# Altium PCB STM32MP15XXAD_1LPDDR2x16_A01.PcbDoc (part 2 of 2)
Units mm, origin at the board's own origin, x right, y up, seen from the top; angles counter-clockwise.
Board outline 86 x 120 mm, 4 copper layers (Top Layer, Signal Layer 1, Signal Layer 2, Bottom Layer), stack 1.571 mm thick; 88 components, 79 nets, 759 pads, 355 vias.
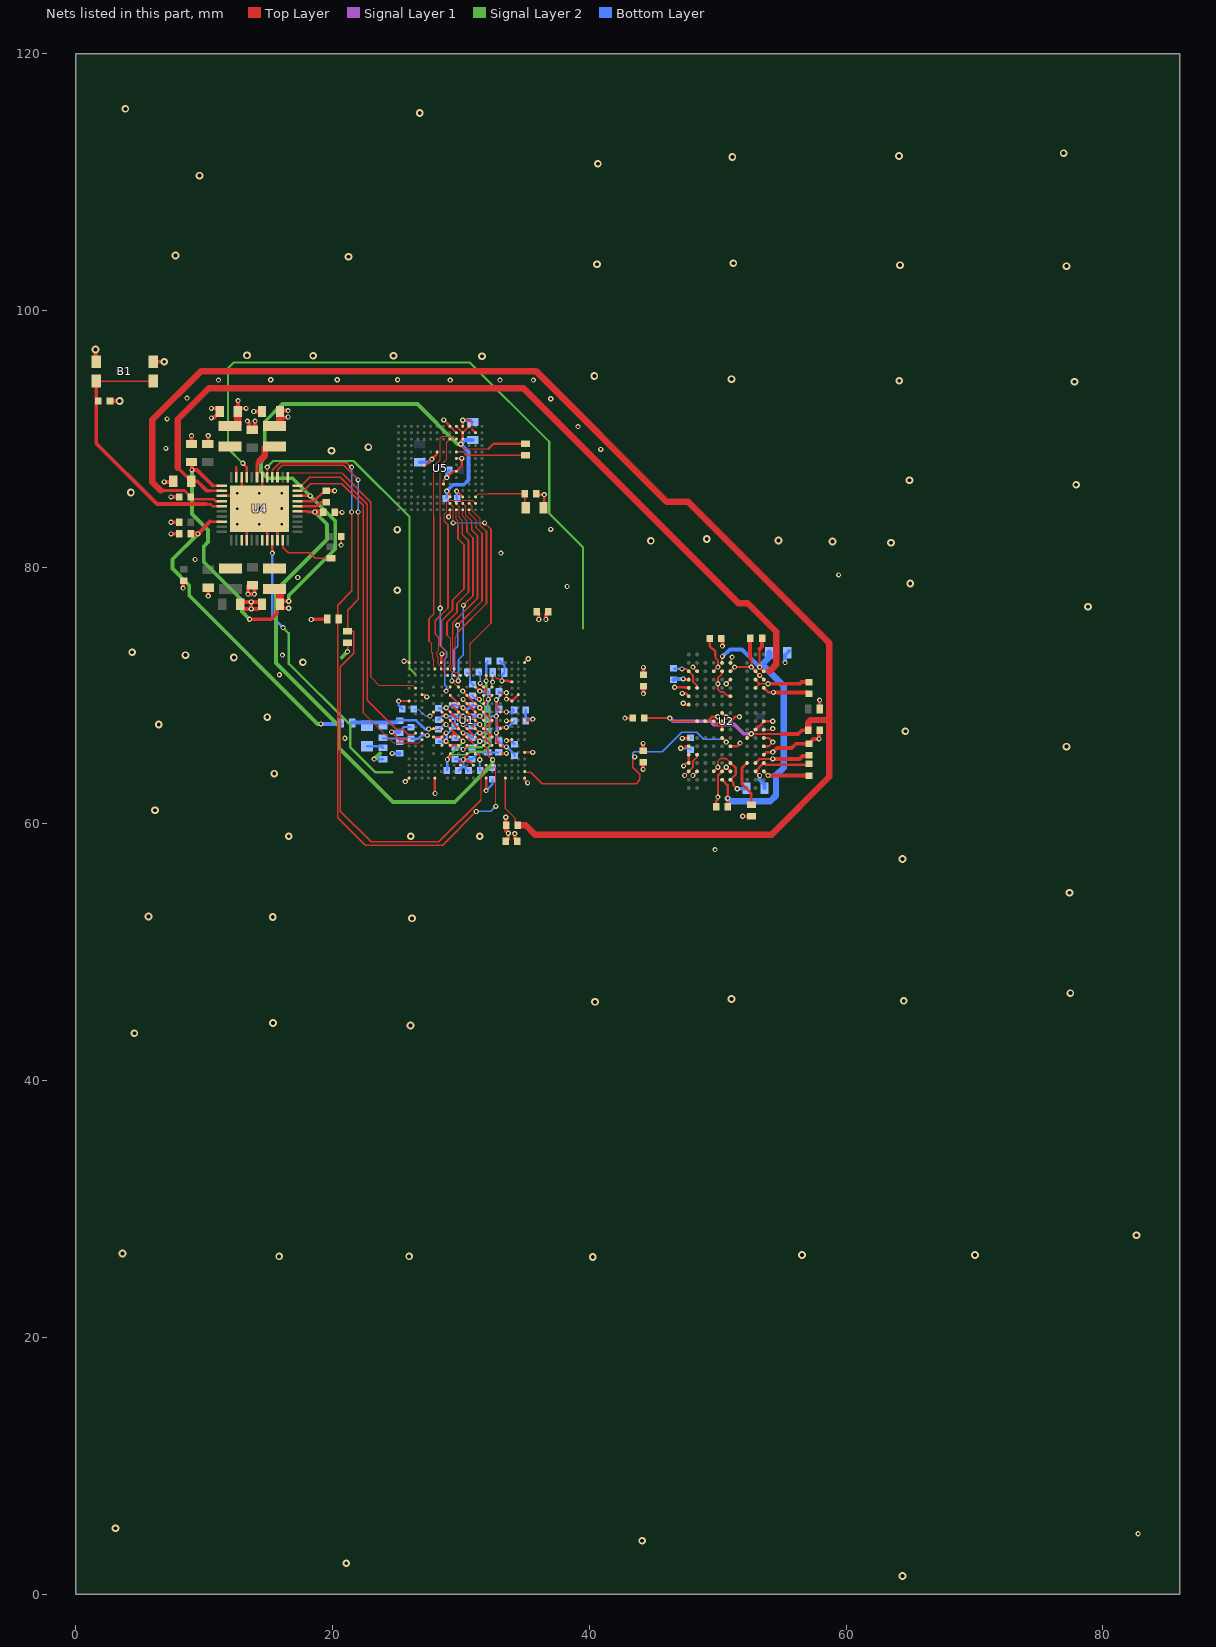
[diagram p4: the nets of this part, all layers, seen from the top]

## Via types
v1: diameter 0.4, hole 0.2, Top Layer to Bottom Layer, tented both sides, 276 vias
v2: diameter 0.6, hole 0.3, Top Layer to Bottom Layer, tented both sides, 74 vias
v3: diameter 0.4, hole 0.2, Top Layer to Bottom Layer, 3 vias
v4: diameter 0.4, hole 0.2, Top Layer to Signal Layer 1, tented top, 2 vias

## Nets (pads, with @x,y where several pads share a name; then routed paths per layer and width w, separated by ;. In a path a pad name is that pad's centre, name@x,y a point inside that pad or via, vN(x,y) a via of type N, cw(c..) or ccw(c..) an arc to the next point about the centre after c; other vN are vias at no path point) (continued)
DDR_DQS1_P: U1.V19 U2.G6 | length 20.7
  Top Layer w0.1: U1.V19@34.97,64.08 U1.V19@34.975,64.075 35,64.05 35.45,64.05 36.355,63.145 39.97,63.145 43.645,63.145 43.955,63.455 43.955,63.87 43.396,64.429 43.396,65.071 v1(43.55,65.225) ; U2.G6@50.35,66.7 v1(50.675,66.375)
  Bottom Layer w0.1: v1(43.55,65.225) 43.396,65.379 43.396,65.521 43.504,65.629 45.704,65.629 47.215,67.14 48.385,67.14 48.94,66.585 50.465,66.585 v1(50.675,66.375)
eMMC_SDIO2_D0: U1.1A4 U5.A3 | length 15.5
  Top Layer w0.09: v1(29.3,71.15) 29.8,70.65 29.825,70.625 29.875,70.625 U1.1A4@29.875,70.645 ; U5.A3@30.65,84.475 30.65,84.2 31.188,83.662 31.188,83.087
  Top Layer w0.13: v1(29.75,75.475) 31.65,77.375 31.65,82.625 31.188,83.087
  Bottom Layer w0.13: v1(29.3,71.15) 29.3,71.725 29.475,71.9 29.475,73.575 29.75,73.85 v1(29.75,75.475)
eMMC_SDIO2_D1: U1.C8 U5.A4 | length 14.7
  Top Layer w0.09: U1.C8@29.475,71.575 29.8,71.25 v1(29.8,71.15) ; U5.A4@30.15,84.475 30.15,83.95 30.475,83.625 30.475,83.25
  Top Layer w0.13: v1(30.2,77.025) 30.95,77.775 30.95,82.275 30.475,82.75 30.475,83.25
  Bottom Layer w0.09: 30.175,73.15 30.2,73.175
  Bottom Layer w0.13: v1@29.825,71.15 29.825,72.8 30.175,73.15 ; 30.2,73.175 v1(30.2,77.025)
eMMC_SDIO2_D2: U1.C7 U5.A5 | length 14.2
  Top Layer w0.09: 28.525,74.4 28.525,73.775 28.875,73.425 28.875,72.975 28.725,72.825 28.725,71.815 28.965,71.575 U1.C7@28.975,71.575 ; U5.A5@29.65,84.475 29.65,83.725 29.775,83.6 29.775,83.25
  Top Layer w0.13: 28.525,74.4 28.525,75.85 29.35,76.675 29.35,77.425 30.25,78.325 30.25,81.75 29.775,82.225 29.775,83.25
eMMC_SDIO2_D3: U1.B6 U5.B2 | length 16.3
  Top Layer w0.09: 28.275,73.85 28.275,73.55 28.17,73.445 28.17,73.059 28.23,72.999 28.23,72.474 28.374,72.33 28.425,72.33 28.475,72.28 U1.B6@28.475,72.075 ; 28.7,83.6 28.7,84.125 28.9,84.325 28.9,85.064 29.061,85.225 30.9,85.225 U5.B2@31.15,84.975
  Top Layer w0.13: 28.275,73.85 28.275,74.525 28,74.8 28,75.825 29,76.825 29,83.3 28.7,83.6
eMMC_SDIO2_D4: U1.B8 U5.B3 | length 14.5
  Top Layer w0.09: U1.B8@29.475,72.075 29.56,72.16 29.56,74.535 29.725,74.7 29.725,74.9 ; U5.B3@30.65,84.975 30.65,84.965 30.9,84.715 30.9,84.386 31.5,83.786 31.5,83.275
  Top Layer w0.13: 29.725,74.9 32,77.175 32,82.775 31.5,83.275
eMMC_SDIO2_D5: U1.C9 U5.B4 | length 15.3
  Top Layer w0.09: 29.39,74.71 29.39,72.336 29.23,72.176 29.23,71.95 29.355,71.825 29.725,71.825 U1.C9@29.975,71.575 ; U5.B4@30.15,84.975 30.4,84.725 30.4,84.05 30.85,83.6 30.85,83.25
  Top Layer w0.1: 29.39,74.71 29.39,75.665
  Top Layer w0.13: 29.39,75.665 31.3,77.575 31.3,82.45 30.85,82.9 30.85,83.25
eMMC_SDIO2_D6: U1.B7 U5.B5 | length 14.2
  Top Layer w0.09: 28.925,74.715 29.22,74.42 29.22,72.445 28.975,72.2 U1.B7@28.975,72.075 ; U5.B5@29.65,84.975 29.65,84.965 29.89,84.725 29.89,83.86 30.1,83.65 30.1,83.25
  Top Layer w0.13: 28.925,74.715 28.925,75.725 29.7,76.5 29.7,77.166 30.6,78.066 30.6,82.05 30.1,82.55 30.1,83.25
eMMC_SDIO2_D7: U1.C10 U5.B6 | length 16.9
  Top Layer w0.09: U5.B6@29.15,84.975 29.4,84.725 v1(29.4,83.45) ; U1.C10@30.475,71.575 30.72,71.82 30.72,74.02
  Top Layer w0.13: 30.72,74.02 32.35,75.65 32.35,82.95 v1(31.85,83.45)
  Bottom Layer w0.09: v1(29.4,83.45) v1(31.85,83.45)
GND: B1.1 B1.2 C1.1 C2.1 C3.1 C4.1 C5.1 C6.1 C7.1 C8.1 C9.1 C10.2 C11.2 C12.2 C13.1 C14.1 C15.2 C16.2 C17.2 C18.1 C19.2 C20.2 C21.2 C22.2 C23.2 C24.2 C25.1 C26.2 C27.1 C28.2 C29.1 C30.1 C31.1 C32.1 C33.1 C34.1 C35.1 C36.1 C37.1 C38.1 C39.1 C40.1 C41.1 C42.1 C43.1 C44.1 C45.1 C46.1 C47.1 C48.1 C49.1 C50.1 C51.2 C52.1 C53.1 C54.1 C55.1 C56.1 C57.1 C58.1 C59.1 C60.1 C61.1 C78.1 C79.1 C80.1 C81.1 C82.1 C83.1 R1.2 R14.1 R31.2 U1.1A6 U1.1B8 U1.1C3 U1.1C5 U1.1C7 U1.1D2 U1.1D4 U1.1D6 U1.1E3 U1.1E5 U1.1E7 U1.1F4 U1.1F6 U1.1G1 U1.1G2 U1.1G5 U1.1G7 U1.1H2 U1.1H3 U1.1H4 U1.1H6 U1.1H8 U1.1J5 U1.1J9 U1.A1 U1.A6 U1.A19 U1.C14 U1.D17 U1.F3 U1.F18 U1.G1 U1.G17 U1.K17 U1.K19 U1.N1 U1.N17 U1.R19 U1.U9 U1.U11 U1.W1 U1.W5 U1.W13 U1.W19 U2.C2 U2.C5 U2.C6 U2.C9 U2.D1 U2.D10 U2.E1 U2.E10 U2.F5 U2.G10 U2.H2 U2.J1 U2.J5 U2.J8 U2.L10 U2.M5 U2.N1 U2.N10 U2.P1 U2.P10 U2.R2 U2.R5 U2.R6 U2.R9 U4.6 U4.10 U4.15 U4.26 U4.30 U4.32 U4.41 U4.ep U5.A6 U5.C4 U5.E7 U5.G5 U5.H10 U5.J5 U5.K8 U5.N2 U5.N5 U5.P4 U5.P6 | length 156.4
  Top Layer w0.09: 30.675,91.45 30.9,91.225 30.9,90.725
  Top Layer w0.12: U1.1C5@30.51,69.34 U1.1C5@30.52,69.33 ; U1.C14@32.475,71.575 32.559,71.575 32.834,71.3 33.025,71.3 33.188,71.138 v1@33.25,71.075 ; U2.J8@49.05,67.965 U2.J8@49.165,67.965 ; U2.M5@50.96,69.95 U2.M5@51,69.95 U2.M5@51,69.985 ; C11.2@52.525,74.435 C11.2@52.56,74.47
  Top Layer w0.15: U1.A19@34.97,72.58 v1@35.258,72.867 ; v1(48.075,72.225) U2.R9@48.4,71.9 ; v1(50.025,62.1) 50.025,63.775 ; U2.R6@50.35,71.9 50.35,71.7 50.025,71.375 v1(50.025,70.925) 50.025,70.479 50.229,70.275 50.475,70.275 50.75,70 50.95,70 U2.M5@51,69.95 ; v1(51.325,72.225) v1(52.625,72.225) 52.625,72.875
  Top Layer w0.175: B1.1@1.55,96.05 B1.1@1.6,96 B1.1@1.6,96.25 ; C60.1@7.55,86.65 C60.1@7.6,86.7 ; C32.1@8.375,78.9 C32.1@8.425,78.95 ; C18.1@10.3,89.6 C18.1@10.325,89.625 ; C29.1@10.975,92.375 C29.1@11.225,92.125 ; C40.1@13.025,77.3 C40.1@12.825,77.1 13.175,76.75 ; C33.1@13.75,90.7 C33.1@13.975,90.925 ; C31.1@13.775,78.6 C31.1@13.925,78.45 ; 14.175,76.75 C38.1@14.525,77.1 C38.1@14.325,77.3 ; C52.1@20.175,84.275 v1(20.75,84.275) ; v1(20.675,81.725) C51.2@20.675,82.4 ; v1(24.6,67.175) 25.2,66.575 U1.N1@25.975,66.575 ; v1(25.15,69.575) U1.G1@25.975,69.575 ; v1(25.575,72.675) 25.875,72.675 U1.A1@25.975,72.575 ; v1(25.675,63.3) 25.7,63.3 U1.W1@25.975,63.575 ; U1.F3@26.975,70.075 27.175,70.075 v1(27.35,69.9) v1@27.4,69.9 ; U5.H10@27.15,87.975 27.3,87.975 v1(27.75,88.425) 28.15,88.825 U5.K8@28.15,88.975 ; U1.1G1@27.875,66.775 U1.1G2@28.525,66.775 ; v1@27.975,62.425 U1.W5@27.975,63.575 ; U1.A6@28.475,72.575 28.475,73.2 v1(28.525,73.25) ; U1.1H2@28.525,66.125 v1(28.85,66.45) ; U1.1D2@28.575,68.675 v1(28.85,68.4) U1.1E3@29.175,68.075 U1.1F4@29.825,67.425 30.162,67.088 U1.1G5@30.475,66.775 U1.1H6@31.125,66.125 ; U5.E7@28.65,86.475 28.65,86.725 v1(28.9,86.975) 29.4,87.475 U5.G5@29.65,87.475 30.075,87.9 v1(30.075,88.475) U5.J5@29.65,88.475 ; v1(28.675,91.475) 29.15,91 U5.P6@29.15,90.975 U5.N5@29.65,90.475 ; v1(28.85,67.1) U1.1G2@28.525,66.775 ; v1@28.9,66.425 v1@28.9,66.4 ; v1(29.05,83.925) 29.15,84.025 U5.A6@29.15,84.475 ; U1.1C3@29.225,69.325 U1.1D4@29.825,68.725 30.162,68.388 U1.1E5@30.475,68.075 U1.1F6@31.125,67.425 31.462,67.088 U1.1G7@31.775,66.775 U1.1H8@32.425,66.125 ; v1(29.675,85.925) 29.7,85.925 U5.C4@30.15,85.475 ; U1.1H4@29.825,66.125 U1.1H3@29.175,66.125 v1@28.9,66.4 ; U1.U9@29.975,64.575 29.975,64.825 30.188,65.038 30.2,65.05 30.212,65.038 30.367,64.883 30.668,64.883 U1.U11@30.975,64.575 ; U5.P4@30.15,90.948 U5.P4@30.15,90.975 v1(30.15,91.45) 30.675,91.45 ; v1@30.175,65.075 U1.1J5@30.525,65.425 ; v1@30.2,69.625 30.225,69.625 U1.1C5@30.475,69.375 U1.1C5@30.51,69.34 ; U1.1C5@30.52,69.33 30.825,69.025 ; 30.83,69.02 U1.1D6@31.125,68.725 31.462,68.388 U1.1E7@31.775,68.075 ; 30.9,90.725 U5.N2@31.15,90.475 ; U1.1A6@31.15,70.675 v1(31.475,70.35) ; U1.1C7@31.775,69.375 32.125,69.725 v1@32.15,69.75 ; v1(31.975,62.6) U1.W13@31.975,63.575 ; v1(32.15,69.7) v1@32.15,69.75 ; U1.1B8@32.425,70.025 v1@32.15,69.75 ; U1.1J9@33.075,65.475 33.525,65.475 v1(33.55,65.5) ; v1@33.125,81 v1(33.125,81.1) ; v1(33.2,71.15) 33.673,71.15 33.748,71.075 U1.D17@33.975,71.075 ; C8.1@33.5,59.925 C8.1@33.525,59.9 ; v1(33.55,68.025) 33.925,68.025 U1.K17@33.975,68.075 ; v1(33.55,69.725) 33.825,69.725 U1.G17@33.975,69.575 ; v1@33.575,66.575 33.55,66.55 33.575,66.525 33.6,66.5 33.9,66.5 U1.N17@33.975,66.575 ; U1.W19@34.975,63.575 34.975,63.425 v1(35.2,63.2) ; U1.K19@34.975,68.075 35.5,68.075 v1(35.6,68.175) ; C82.1@35.875,85.725 35.95,85.65 v1(36.5,85.65) 36.5,84.675 C83.1@36.45,84.625 ; C23.2@44.2,64.796 C23.2@44.215,64.81 ; v1(47.35,64.525) 47.575,64.75 U2.D10@47.75,64.75 U2.D10@47.725,64.725 ; 50.025,63.775 U2.C6@50.35,64.1 v1(50.675,64.425) ; C20.2@50.275,74.45 50.275,74.425 C20.2@50.375,74.325 ; v1(50.675,64.425) U2.C5@51,64.1 ; U2.J1@53.6,68 v1(54.3,68) ; U1.1G2@28.525,66.775 v1(28.85,66.45) ; v1(28.85,66.45) v1@28.9,66.4 ; v1(28.85,66.45) 28.875,66.425 v1@28.9,66.4
  Top Layer w0.2: U4.15@11.375,85.55 12.6,85.55 U4.ep@13.325,85.55 ; U4.10@12.925,87 12.925,85.95 U4.ep@13.325,85.55 ; U4.26@13.325,82.1 13.325,83.55 U4.ep@14.325,84.55 ; U4.6@14.525,87 14.525,85.75 14.525,84.75 U4.ep@14.325,84.55 ; U4.30@14.925,82.1 U4.ep@14.925,83.95 ; U4.32@15.725,82.1 15.725,83.15 U4.ep@14.925,83.95 ; U4.41@17.275,85.15 18.575,85.15 19.375,85.95 C43.1@19.525,85.95 ; U1.1D2@28.57,68.68 U1.1D2@28.575,68.675 ; U1.G17@33.975,69.575 34.46,70.06 34.46,70.075 U1.F18@34.46,70.08 ; U1.R19@34.97,65.58 34.975,65.58 v1@35.6,65.58 ; v1(42.775,68.25) C26.2@43.375,68.25 ; v1(46.65,70.65) 47.5,70.65 47.55,70.6 U2.N10@47.75,70.6 ; v1@47.25,66.7 U2.G10@47.75,66.7 ; v1(47.325,69.4) 47.425,69.3 U2.L10@47.75,69.3 ; v1(47.325,71.3) 47.375,71.3 47.425,71.25 U2.P10@47.75,71.25 ; U2.D10@47.75,64.75 U2.E10@47.75,65.4 ; v1(48.075,63.775) U2.C9@48.4,64.1 ; U2.J8@49.165,67.965 49.55,68.35 v1(50,68.35) ; C10.2@49.88,61.35 49.88,61.78 50.025,61.925 v1(50.025,62.1) ; U2.F5@51,66.05 51.5,66.05 v1(51.75,66.3) ; U2.J5@51,68 51.35,68.35 v1(51.7,68.35) ; U2.R5@51,71.9 v1(51.325,72.225) ; v1(52.625,72.225) U2.R2@52.95,71.9 v1(53.275,71.575) U2.P1@53.6,71.25 ; U2.H2@52.95,67.35 U2.J1@53.6,68 ; v1(53.275,63.775) U2.C2@52.95,64.1 53.55,64.7 53.6,64.7 53.675,64.7 53.75,64.625 57.1,64.625 C12.2@57.125,64.6 ; U2.E1@53.6,65.4 53.8,65.6 v1(54.3,65.6) ; U2.N1@53.6,70.6 53.95,70.25 v1@54.345,70.25 ; U4.ep@13.325,85.55 v1(14.3,84.575) U4.ep@14.325,84.55 ; U4.ep@14.325,84.55 U4.ep@14.925,83.95
  Top Layer w0.25: v4(7.425,82.6) C49.1@8.075,82.6 ; v4(7.425,83.5) C41.1@8.075,83.5 ; v1(10.325,77.75) C39.1@10.325,78.4 ; C43.1@19.525,85.95 v1(20.175,85.95)
  Top Layer w0.3: B1.1@1.55,96.05 v2(1.55,96.95) ; C44.1@2.675,92.95 v2(3.425,92.95) ; B1.2@6.05,96 v2(6.9,96) ; v1(6.9,86.65) C60.1@7.55,86.65 ; v1(7.425,85.475) C27.1@8.075,85.475 ; v1(8.375,78.375) C32.1@8.375,78.9 ; C42.1@9.025,89.6 v1(9.025,90.25) ; C18.1@10.325,89.625 v1(10.325,90.25) ; v1(10.575,91.625) 10.725,91.625 C29.1@11.225,92.125 ; v1(10.575,92.375) C29.1@10.975,92.375 ; C40.1@13.025,77.3 v1(13.675,77.3) ; 13.175,76.75 v1(13.675,76.75) ; v1(13.375,91.375) 13.55,91.2 C33.1@13.55,90.925 ; v1(13.425,77.9) C31.1@13.425,78.55 ; v1(13.875,92.125) C34.1@14.525,92.125 ; v1(13.925,77.9) C31.1@13.925,78.45 ; C33.1@13.975,90.925 v1(13.975,91.375) ; 14.175,76.75 v1(13.675,76.75) ; C38.1@14.325,77.3 v1(13.675,77.3) ; C24.2@33.5,58.65 33.7,58.85 v1(33.7,59.275) 33.525,59.45 C8.1@33.525,59.9 ; C8.1@33.5,59.925 v1(33.5,60.525) ; v1(36.625,75.925) 36.625,76.35 C21.2@36.8,76.525 ; v1(44.2,64.25) C23.2@44.2,64.796 ; C22.2@44.225,71.625 v1(44.225,72.2) ; v3(50.375,73.85) C20.2@50.375,74.325 ; v1(51.95,60.6) R31.2@52.625,60.6 ; C11.2@52.525,74.435 52.525,72.975 52.625,72.875 ; v1(54.3,65.6) 54.625,65.925 55.765,65.925 56.09,66.25 57.1,66.25 57.113,66.263 57.475,66.625 v1(57.9,66.625) 57.9,67.225 57.963,67.288 C28.2@57.975,67.3 ; v1@54.345,70.25 v1(54.35,70.25) 57.025,70.25 C19.2@57.125,70.15 ; R14.1@57.95,68.975 v1(57.95,69.65) ; v1(13.675,76.75) v1(13.675,77.3)
  Top Layer w0.33: v1(13.425,77.9) v1(13.925,77.9)
  Bottom Layer w0.175: C2.1@25.075,67.175 C2.1@25.2,67.175 ; v1(25.15,69.575) 25.15,69.25 C1.1@25.45,68.95 ; C2.1@25.175,67.075 25.191,67.14 C2.1@25.2,67.175 ; C50.1@25.225,65.5 C50.1@25.25,65.525 ; C2.1@25.25,67.125 C2.1@25.2,67.175 ; C61.1@26.125,67.55 25.575,67.55 C2.1@25.2,67.175 ; C36.1@28.25,68.125 28.525,68.4 v1(28.85,68.4) C35.1@29.55,68.4 ; C47.1@28.275,66.425 28.3,66.4 28.85,66.4 v1@28.925,66.4 ; v1@28.825,66.975 v1@28.9,67.05 ; v1@28.9,66.45 v1@28.9,67.05 ; v1@28.925,67.075 v1@28.9,67.05 ; C46.1@29.525,67.625 29.55,67.65 C35.1@29.55,68.35 C35.1@29.55,68.4 ; C4.1@29.55,65.025 29.562,65.037 29.575,65.05 v1@30.2,65.05 ; C46.1@29.55,67.6 29.625,67.6 30.15,67.075 v1@30.175,67.05 ; C46.1@29.55,67.625 29.537,67.612 28.975,67.05 v1@28.9,67.05 ; v1(29.675,85.925) 29.675,85.4 C80.1@29.725,85.35 ; C48.1@29.825,64.15 30.2,64.525 ; v1@30.2,67.05 30.525,67.05 C13.1@30.8,66.775 ; C6.1@30.475,71.75 30.725,71.5 30.725,71.075 C5.1@30.9,70.9 31.45,70.35 v1(31.475,70.35) ; C3.1@30.575,64.15 30.2,64.525 ; C81.1@30.775,91.45 C81.1@30.925,91.3 ; C13.1@30.85,66.675 C13.1@30.875,66.7 31.275,67.1 v1(31.475,67.1) 32,67.1 C58.1@32.125,67.225 ; v1(31.475,68.4) 30.925,68.4 C14.1@30.875,68.35 30.825,68.4 v1(30.175,68.4) 29.552,68.4 C35.1@29.55,68.4 ; v1@31.5,68.35 31.512,68.362 C57.1@32.075,68.925 ; v1@31.5,70.3 32.05,70.3 C53.1@32.075,70.325 C53.1@32.125,70.275 ; v1(31.975,62.6) 32.475,63.1 C7.1@32.475,63.475 ; C57.1@32.075,68.95 C57.1@32.075,68.925 ; C30.1@32.1,65.625 C30.1@32.1,65.575 ; C57.1@32.15,69 C57.1@32.125,68.975 ; C53.1@32.15,70.25 C53.1@32.125,70.275 ; C45.1@33.05,72.7 33.4,72.35 R1.2@33.4,71.8 33.2,71.6 v1(33.2,71.15) ; v1(33.55,65.5) 33.025,65.5 C59.1@32.95,65.575 C30.1@32.1,65.575 ; v1(33.55,66.5) 33.9,66.5 C55.1@34.175,66.225 ; C56.1@35.05,68.875 C54.1@35.05,68.025 35.2,68.175 v1(35.6,68.175) ; v1(47.25,66.67) 47.87,66.67 C15.2@47.9,66.7 ; 30.2,64.525 v1(30.2,65.025) v1@30.2,65.05 ; v1@30.2,65.05 C37.1@30.875,65.05 31.4,65.575 C30.1@32.1,65.575 ; C57.1@32.075,68.925 32.087,68.937 C57.1@32.125,68.975 ; C57.1@32.125,68.975 32.125,69.7 C53.1@32.125,70.275
  Bottom Layer w0.3: v1(24.6,67.175) C2.1@25.2,67.175 ; v1(24.65,65.5) C50.1@25.225,65.5 ; C79.1@26.8,88.175 27.5,88.175 v1(27.75,88.425) ; v1(28.9,86.975) 28.9,87.35 C78.1@29.1,87.55 ; v1(30.15,91.45) C81.1@30.775,91.45 ; C16.2@46.575,71.225 46.65,71.3 v1(47.325,71.3) ; v1(53.275,63.775) 53.275,63.45 53.65,63.075 C25.1@53.65,62.8 ; v1(55.25,72.575) 55.25,73.155 C9.1@55.43,73.335 C9.1@55.573,73.479
  other v1: 82.75,4.725 49.8,58 28,62.375 35.6,65.575 20.975,66.675 30.175,67.1 30.175,69.7 15.875,71.625 35.25,72.875 16.1,73.15 17.3,79.2 59.425,79.4 9.3,80.6 37,82.95 12.6,83.35 14.3,83.35 16.05,83.35 12.575,84.55 16.05,84.575 12.6,85.75 14.3,85.75 16.05,85.75 40.9,89.175 7.025,89.25 39.125,90.95 7.125,91.55 37,93.125 8.675,93.175 11.125,94.575 29.175,94.575 33.05,94.575 35.65,94.575 15.2,94.6 20.375,94.6 25.075,94.6
  other v2: 64.4,1.425 21.075,2.425 44.125,4.175 3.1,5.15 40.275,26.275 15.85,26.325 25.975,26.325 56.575,26.425 70.05,26.425 3.65,26.55 82.625,27.975 4.575,43.7 26.075,44.3 15.375,44.5 40.45,46.15 64.5,46.225 51.075,46.375 77.475,46.825 26.2,52.65 15.35,52.75 5.675,52.8 77.4,54.65 64.4,57.275 16.6,59.05 26.1,59.05 31.475,59.05 6.175,61.075 15.475,63.925 77.175,66.025 64.625,67.225 6.475,67.75 14.925,68.325 17.7,72.6 12.325,72.975 8.55,73.15 4.4,73.375 78.85,76.925 25.05,78.2 65,78.725 63.5,81.9 58.95,82 44.8,82.05 54.75,82.075 49.15,82.2 25.05,82.925 4.3,85.825 77.925,86.425 64.95,86.775 19.925,89.075 22.8,89.35 77.8,94.45 64.15,94.525 51.075,94.65 40.4,94.9 31.65,96.425 18.5,96.475 24.75,96.475 13.35,96.5 77.175,103.45 64.2,103.525 40.6,103.6 51.225,103.675 21.25,104.175 7.775,104.275 9.65,110.5 40.675,111.425 51.15,111.95 64.125,112.025 76.95,112.25 26.8,115.375 3.875,115.7
  other v3: 38.275,78.5
I2C4_SCL: R37.2 U1.U14 U4.4 | length 52.6
  Top Layer w0.09: 15.3,87.54 15.3,87.025 U4.4@15.325,87 ; U1.U14@32.475,64.575 32.72,64.33 v1@32.72,61.425
  Top Layer w0.1: 15.3,87.54 15.885,88.125 21.1,88.125 21.425,87.8 v1(21.5,87.8) ; v1(21.5,84.3) 21.5,78.15 20.4,77.05 20.4,75.95 20.4,60.5 22.55,58.35 28.575,58.35 v1(31.2,60.975)
  Bottom Layer w0.1: v1(21.5,84.3) v1(21.5,87.8) ; v1(31.2,60.975) 32.325,60.975 v1(32.725,61.375)
I2C4_SDA: R38.2 U1.U13 U4.3 | length 50.7
  Top Layer w0.09: U4.3@15.725,87 15.725,87.575 ; 31.575,61.9 31.575,63.762 31.72,63.907 31.72,64.166 31.975,64.421 U1.U13@31.975,64.575
  Top Layer w0.1: 15.725,87.575 16.075,87.925 20.875,87.925 v1(22,86.8) ; v1@22.025,84.275 22.025,77.5 21.175,76.65 R38.2@21.175,75 21.675,75 21.675,73.3 20.625,72.25 20.625,61 23.025,58.6 28.275,58.6 31.575,61.9
  Bottom Layer w0.1: v1(22,84.3) v1(22,86.8)
NetB1_3: B1.3 B1.4 C44.2 U4.17 | length 21.5
  Top Layer w0.1: B1.3@1.325,94.775 B1.3@1.6,94.5 B1.4@6.05,94.5
  Top Layer w0.2: 10.125,84.9 10.525,84.9 10.675,84.75 U4.17@11.375,84.75
  Top Layer w0.3: B1.3@1.6,94.45 1.6,92.95 1.6,89.65 6.325,84.925 10.15,84.925
NetC1_2: C1.2 U1.1D1 | length 1.9
  Top Layer w0.09: v1(27.6,68.4) 27.65,68.4 27.925,68.675 U1.1D1@27.925,68.65
  Bottom Layer w0.09: C1.2@26.375,68.95 26.7,68.95 27.225,68.425 27.55,68.425 27.587,68.388 v1@27.6,68.375
NetC2_2: C2.2 L5.2 R41.1 R42.2 U1.1F1 U1.1F2 | length 7.4
  Top Layer w0.09: v1@27.5,67.375 27.875,67.375 28.525,67.375 U1.1F2@28.575,67.375
  Bottom Layer w0.2: C2.2@25.075,68.075 25.25,68.075 26.525,68.075 27.2,67.4 v1(27.5,67.4)
  Bottom Layer w0.3: R42.2@21.55,67.9 22.7,67.9 23.925,67.9 24.9,67.9 C2.2@25.075,68.075
NetC3_2: C3.2 U1.1J6 | length 1.7
  Top Layer w0.09: v1@31.5,65 v1@31.5,65.1
  Top Layer w0.1: U1.1J6@31.175,65.425 31.4,65.425 31.475,65.35 v1(31.475,65) v1@31.5,65
  Bottom Layer w0.1: C3.2@31.475,64.175 v1(31.475,65)
  Bottom Layer w0.175: C3.2@31.5,64.2 31.512,64.188 C3.2@31.525,64.175
NetC6_2: C6.2 U1.1A7 U1.1B7 | length 2.1
  Top Layer w0.2: v1(31.5,70.95) U1.1A7@31.775,70.675 31.95,70.5 31.95,70.2 U1.1B7@31.775,70.025
  Bottom Layer w0.1: C6.2@31.4,71.85 31.5,71.75 v1(31.5,70.95)
NetC43_2: C43.2 U4.40 | length 2.4
  Top Layer w0.2: U4.40@17.275,84.75 18.775,84.75 19.075,85.05 C43.2@19.525,85.05
NetC82_2: C82.2 C83.2 U5.C2 | length 5.1
  Top Layer w0.09: U5.C2@31.15,85.475 31.4,85.725 32.15,85.725
  Top Layer w0.1: 32.15,85.725 C82.2@34.975,85.725 34.975,84.7 C83.2@35.05,84.625
NetL1_1: L1.1 U4.7 | length 3.2
  Top Layer w0.2: U4.7@14.125,87 14.125,88.1 14.325,88.3
  Top Layer w0.5: 14.325,88.3 14.725,88.7 14.725,89.3 14.825,89.4 L1.1@15.325,89.4
NetL2_1: L2.1 U4.11 | length 0.8
  Top Layer w0.2: U4.11@12.525,87 12.525,87.8
NetL3_1: L3.1 U4.29
NetL4_1: L4.1 U4.25
NetL5_1: L5.1 R39.2 | length 1.3
  Bottom Layer w0.2: L5.1@22.7,66.05 23.825,66.05 R39.2@23.925,65.95
NetR1_1: R1.1 U1.1A8 | length 1.1
  Top Layer w0.09: U1.1A8@32.425,70.675 32.425,71 v1(32.475,71.05)
  Bottom Layer w0.175: v1(32.475,71.05) R1.1@32.475,71.8
NetR31_1: R31.1 U2.D3 | length 3.7
  Top Layer w0.2: U2.D3@52.3,64.75 51.9,64.35 51.9,63.1 52.625,62.375 R31.1@52.625,61.5
NetR40_1: R40.1 U5.K5 | length 5.5
  Top Layer w0.1: U5.K5@29.65,88.975 30.175,88.975 30.42,88.73 31.98,88.73 31.985,88.725 R40.1@35.025,88.725
NetR43_1: R43.1 U4.33 | length 4.7
  Top Layer w0.1: U4.33@16.125,82.1 16.125,81.55 16.55,81.125 18.25,81.125 18.675,80.7 R43.1@19.9,80.7
NRST: U1.E2 U4.1 | length 25.2
  Top Layer w0.09: U4.1@16.525,87 16.525,87.35 20.725,87.35 20.85,87.225 ; 23,71.45 23.625,70.825 26.225,70.825 U1.E2@26.475,70.575
  Top Layer w0.1: 20.85,87.225 23,85.075 23,71.45
PA0_WKUP: U1.N3 U4.43 | length 27.8
  Top Layer w0.09: 22.4,68.675 24.75,66.325 26.725,66.325 U1.N3@26.975,66.575
  Top Layer w0.1: 17.775,85.95 18.325,86.5 20.725,86.5 22.4,84.825 22.4,68.675
  Top Layer w0.12: U4.43@17.275,85.95 17.775,85.95
PWR_ON: U1.M2 U4.44 | length 26.4
  Top Layer w0.09: 26.05,66.99 26.39,66.99 U1.M2@26.475,67.075
  Top Layer w0.1: U4.44@17.575,86.35 18.225,87 20.625,87 22.725,84.9 22.725,69.625 24.957,67.392 25.465,67.392 25.853,67.005 26.05,67.005
SDMMC2_CK: U1.1A3 U5.M6 | length 20.8
  Top Layer w0.09: 28.4,83.925 28.4,87.9 28.9,88.4 28.9,89.725 U5.M6@29.15,89.975 ; v1(28.85,70.35) U1.1A3@29.175,70.675 ; v1@28.888,70.287 v1@28.9,70.3
  Top Layer w0.13: v1(28.4,76.8) 28.4,83.925
  Bottom Layer w0.1: 28.75,71.7 28.75,70.853 28.9,70.703 28.9,70.35 v1@28.9,70.275
  Bottom Layer w0.13: v1(28.4,76.8) 28.4,73.9 28.9,73.4 28.9,73.025 28.75,72.875 28.75,71.7
SDMMC2_CMD: U1.B5 U5.M5 | length 20
  Top Layer w0.09: 27.525,74.25 27.753,74.022 27.753,73.378 27.822,73.31 27.822,72.914 27.89,72.845 27.89,72.21 U1.B5@27.975,72.125 ; 27.9,83.975 27.9,87.875 28.4,88.375 28.4,90.064 28.551,90.215 29.41,90.215 U5.M5@29.65,89.975 ; U1.B5@27.975,72.075 U1.B5@27.975,72.125 ; U1.B5@27.975,72.145 U1.B5@27.975,72.125
  Top Layer w0.13: 27.525,74.25 27.525,75.975 27.9,76.35 27.9,83.975
VDD: C38.2 C42.2 C45.2 C46.2 C47.2 C48.2 C80.2 C81.2 L3.2 R37.1 R38.1 R39.1 R40.2 U1.1E2 U1.1F3 U1.1G3 U1.1G4 U1.1J3 U1.C13 U4.13 U4.31 U4.42 U5.C6 U5.M4 U5.N4 U5.P3 U5.P5 | length 122.3
  Top Layer w0.09: C38.2@16.175,77.35 C38.2@15.925,77.1 C38.2@16.225,76.8 ; v1(18.35,75.925) v1@18.375,75.95 ; v1(30,89.575) 30.35,89.225 32.15,89.225
  Top Layer w0.1: v1(21.175,73.425) R38.1@21.175,74.1
  Top Layer w0.12: U4.13@11.075,86.35 U4.13@11.375,86.35
  Top Layer w0.175: v1@9.025,87.6 v1(9.05,87.575) ; C42.2@9.025,88.2 C42.2@9.05,88.175 ; v1@13.45,75.95 v1(13.55,75.95) ; C38.2@15.7,76.875 C38.2@15.925,77.1 ; U1.1E2@28.525,68.075 v1(28.85,67.75) U1.1F3@29.175,67.425 29.5,67.1 ; v1(28.9,85.925) 29.15,85.675 U5.C6@29.15,85.475 ; v1(28.95,65.025) 29.225,65.3 U1.1J3@29.225,65.425 ; U1.1G3@29.175,66.775 29.5,67.1 ; U5.P5@29.65,90.975 U5.N4@30.15,90.475 ; v1(30,89.575) 30,89.825 U5.M4@30.15,89.975 U5.N4@30.15,90.475 ; v1@30.2,66.42 30.172,66.447 29.845,66.775 U1.1G4@29.825,66.775 29.725,66.875 29.5,67.1 ; U5.P3@30.65,90.975 U5.N4@30.15,90.475 ; v1(31.975,71.15) U1.C13@31.975,71.575 ; 32.15,89.225 32.55,89.625 R40.2@35.025,89.625
  Top Layer w0.2: 10.675,86.35 U4.13@11.075,86.35 ; v1(15.325,81.1) U4.31@15.325,82.1 ; U4.42@17.275,85.55 v1(18.275,85.55)
  Top Layer w0.3: C42.2@9.05,88.175 v1(9.05,87.575) 9.45,87.575 10.675,86.35 ; v1(13.55,75.95) 15.225,75.95 15.7,76.425 C38.2@15.7,76.875 ; C38.2@16.175,77.35 v1(16.6,77.35) ; C38.2@16.225,76.8 v1(16.6,76.8) ; v1@18.375,75.95 R37.1@19.6,75.95
  Top Layer w0.6: C38.2@15.925,77.1 L3.2@15.925,78.3
  Signal Layer 2 w0.09: 31.803,69.948 31.803,69.56 32.225,69.137 32.225,69
  Signal Layer 2 w0.1: v1(28.95,65.025) v1@28.975,65.05 ; 29.2,65.4 30.525,65.4
  Signal Layer 2 w0.175: v1@28.9,67.7 30.162,66.437 v1@30.2,66.4 ; v1@28.975,65.025 28.975,65.05 28.975,65.175 29.2,65.4 v1@30.2,66.4 ; v1@30.25,66.35 v1@30.2,66.4 ; 30.525,65.425 30.73,65.63 31.805,65.63 32.225,66.05 32.225,69 ; 31.803,69.948 31.975,70.12 v1(31.975,71.15)
  Signal Layer 2 w0.2: v1(16.15,75.3) 16.6,74.85 16.6,72.5 21.4,67.7 21.4,65.975 23.35,64.025 24.675,64.025
  Signal Layer 2 w0.3: v1(9.05,87.575) 9.05,84.15 10.3,82.9 10.3,81.95 9.975,81.625 9.975,80.4 12.95,77.425 12.95,76.55 v1(13.55,75.95) ; v1(16.6,77.35) 16.6,77.8 20.225,81.425 20.225,83.6 v1(18.275,85.55) 16.9,86.925 14.95,86.925 14.425,87.45 14.425,88.2 14.725,88.5 14.725,91.325 16.1,92.7 26.625,92.7 29.75,89.575 v1(30,89.575) ; 20.725,72.975 v1(21.175,73.425) ; v1(23.25,65.05) 23.7,65.5
  Bottom Layer w0.1: C80.2@28.825,85.35 C80.2@28.9,85.425 ; C45.2@31.975,72.525 C45.2@32.15,72.7
  Bottom Layer w0.175: v1(23.25,65.05) R39.1@23.925,65.05 ; C47.2@28.3,67.375 28.625,67.7 28.85,67.7 v1@28.9,67.7 ; C80.2@28.9,85.425 v1(28.9,85.925) ; C48.2@28.925,64.2 28.95,64.225 v1(28.95,65.025) ; C46.2@29.55,66.675 29.925,66.675 30.162,66.437 v1@30.2,66.4 ; v1(31.975,71.15) C45.2@31.975,72.525
  Bottom Layer w0.2: v1(15.325,81.1) 15.325,76.125 v1(16.15,75.3)
  Bottom Layer w0.3: v1(28.9,85.925) 29.4,86.425 30.225,86.425 30.6,86.8 30.6,88.975 v1(30,89.575) 30.325,89.9 C81.2@30.925,89.9
  other v1: 30.175,66.45
VDD1_DDR: C9.2 C10.1 C11.1 C12.1 C60.2 U2.B6 U2.C1 U2.R1 U2.T6 U4.14 | length 97.5
  Top Layer w0.15: U2.T6@50.35,72.55 50.35,73.025 v1(50.375,73.05) ; v1(53.275,72.225) 53.275,73.625
  Top Layer w0.175: 10.375,85.95 U4.14@11.375,85.95
  Top Layer w0.2: U2.B6@50.35,63.45 50.785,63.015 50.785,62 v1@50.785,61.995 ; C10.1@50.78,61.35 v1@50.78,61.99 ; U2.C1@53.6,64.1 v1(53.925,63.775)
  Top Layer w0.3: 7.95,87.75 C60.2@9,86.7 9.475,86.7 10.225,85.95 10.375,85.95 ; v1(53.275,72.225) U2.R1@53.6,71.9 54.05,71.9 ; 53.275,73.625 53.45,73.8 53.45,74.46 C11.1@53.46,74.47 ; v1(53.925,63.775) C12.1@57.125,63.775
  Top Layer w0.5: 7.95,87.75 7.95,91.525 10.375,93.95 34.875,93.95 51.625,77.2 52.35,77.2 54.575,74.975 54.575,72.425 54.05,71.9
  Bottom Layer w0.3: v1@50.385,73.03 50.39,73.035 50.955,73.6 51.9,73.6 v1(53.275,72.225) ; v1(53.925,63.775) 54.55,63.775
  Bottom Layer w0.5: v1(50.775,62) 51,61.775 54.1,61.775 54.55,62.225 54.55,63.775 55.15,64.375 55.15,70.75 53.675,72.225 v1(53.275,72.225) 54.03,72.98 C9.2@54.03,73.335
VDD2_DDR: C15.1 C16.1 C17.1 C19.1 C20.1 C21.1 C22.1 C23.1 C24.1 C25.2 C29.2 C53.2 C54.2 C55.2 C56.2 C57.2 C58.2 C59.2 L2.2 U1.1B9 U1.1D9 U1.1F9 U1.1H9 U2.B5 U2.C7 U2.C10 U2.D2 U2.D5 U2.E9 U2.F1 U2.F10 U2.G1 U2.H1 U2.H6 U2.J6 U2.J7 U2.K6 U2.M10 U2.N2 U2.N9 U2.P2 U2.P5 U2.R7 U2.R10 U2.T5 U4.9 | length 104.8
  Top Layer w0.09: v1@33.525,66.075 v1@33.575,66.025
  Top Layer w0.12: C23.1@44.2,65.725 C23.1@44.215,65.71 ; v3(47.425,63.775) U2.C10@47.75,64.1 ; v1(50.025,64.425) 50.025,64.9 50.225,65.1 50.675,65.1 51.012,64.763 51.015,64.76 U2.D5@51.015,64.75 ; U2.H1@53.6,67.35 54.225,67.35 v1(54.3,67.425)
  Top Layer w0.15: v1(47.225,72.075) 47.575,72.075 U2.R10@47.75,71.9 48.075,71.575 48.075,71.1 48.4,70.775 U2.N9@48.4,70.6 ; U2.C10@47.75,64.1 48.075,64.425 48.075,64.9 48.4,65.225 U2.E9@48.4,65.4 ; U2.R7@49.7,71.9 v1(50.025,72.225) 50.025,72.75 49.825,72.95 49.825,73.1 ; v1(50.675,70.925) U2.P5@51,71.25 ; U2.T5@51,72.55 50.995,72.555 50.995,72.727 51.125,72.857 v1(51.125,73) ; U2.N2@52.95,70.6 53.275,70.925 v1(53.925,70.925) ; U2.P2@52.985,71.215 53.26,70.94 ; 53.275,65.075 v1(54.3,65.075)
  Top Layer w0.175: C29.2@12.625,92.125 12.65,92.15 C29.2@12.875,92.375 ; v1(32.775,68.4) 32.775,67.725 U1.1F9@33.075,67.425 ; v1(32.775,69.675) 32.775,69.025 U1.1D9@33.075,68.725 33.5,68.725 33.525,68.7 v1(33.55,68.725) ; U1.1B9@33.075,70.025 33.275,70.225 v1(33.55,70.225) ; v1(33.55,67.525) 33.175,67.525 U1.1F9@33.075,67.425 ; v1@33.575,66.025 33.55,66.025 33.175,66.025 U1.1H9@33.075,66.125 32.775,66.425 v1(32.775,67.1) 32.775,67.125 U1.1F9@33.075,67.425 ; U2.B5@51,63.45 51.225,63.225 51.225,63.05 v1(51.525,62.75) ; U2.F1@53.6,66.05 53.975,66.05 v1(54.3,66.375) 53.975,66.7 U2.G1@53.6,66.7
  Top Layer w0.2: v1(13.025,88.1) 13.325,87.8 U4.9@13.325,87 ; v1@47.025,65.9 v1(47.125,65.9) 47.375,65.9 47.525,66.05 U2.F10@47.75,66.05 ; v1(47.25,70.175) 47.525,70.175 U2.M10@47.75,69.95 ; C20.1@49.375,74.45 49.375,73.875 49.825,73.425 49.825,73.1 ; U2.C7@49.7,64.1 v1(50.025,64.425) ; U2.J7@49.7,68 50,67.7 50.35,67.7 ; U2.H6@50.35,67.35 50.35,67.7 ; U2.K6@50.35,68.65 v1(50.675,68.325) U2.J6@50.35,68 50.35,67.7 ; U2.B5@51,63.455 51.42,63.875 51.42,64.345 U2.D5@51.015,64.75 ; U2.D2@52.95,64.75 53.275,65.075
  Top Layer w0.3: C29.2@12.65,92.15 v1(12.65,92.975) ; C29.2@12.875,92.375 v1(13.275,92.375) ; v1(34.2,59.25) 34.2,58.85 C24.1@34.4,58.65 ; C21.1@35.925,76.525 36.075,76.375 v1(36.075,75.925) ; C23.1@44.2,65.725 v1(44.2,66.275) ; v1(44.225,70.15) C22.1@44.225,70.725 ; v1(53.925,70.925) 56.405,70.925 56.53,71.05 C19.1@57.125,71.05 ; v1(54.3,65.075) 56.375,65.075 56.6,65.3 57.075,65.3 C17.1@57.125,65.35
  Top Layer w0.6: L2.2@12.025,91 12.525,91 12.625,91.1 C29.2@12.625,92.1
  Signal Layer 2 w0.175: v1(13.025,88.1) 11.875,89.25 11.875,95.5 12.325,95.95 30.7,95.95 36.888,89.762 36.888,84.187 39.525,81.55 39.525,75.25
  Bottom Layer w0.12: C15.1@47.8,65.9 C15.1@47.9,65.8
  Bottom Layer w0.175: C58.2@32.125,68.125 32.4,68.4 v1(32.775,68.4) ; v1(33.55,70.225) 33.075,70.225 C53.2@32.975,70.325 32.975,69.825 32.8,69.65 C57.2@32.8,69.125 ; C56.2@34.025,68.975 C56.2@34.137,68.863 ; C54.2@34.15,68.025 33.65,67.525 v1(33.55,67.525) 32.8,67.525 ; C56.2@34.15,68.85 C56.2@34.138,68.863 ; C56.2@34.15,68.875 C56.2@34.138,68.863 ; C55.2@34.175,65.325 34.175,65.425 33.6,66 v1(33.55,66) 33.425,66 C59.2@32.95,66.475 32.8,66.625 32.8,67.1 32.8,67.525 ; 32.8,67.525 32.8,68.4 32.8,68.95 C57.2@32.8,69.125 ; C57.2@32.8,69.125 C57.2@32.975,68.95 33.2,68.725 v1(33.55,68.725) 34,68.725 C56.2@34.138,68.863
  Bottom Layer w0.2: C16.1@46.625,72.075 v1(47.225,72.075) ; v1(47.125,65.9) C15.1@47.8,65.9
  Bottom Layer w0.3: v1(51.525,62.75) 52.2,62.75 C25.2@52.25,62.8
VDD_CORE: C13.2 C14.2 C30.2 C34.2 C35.2 C36.2 C37.2 L1.2 U1.1B3 U1.1B5 U1.1C4 U1.1C6 U1.1D3 U1.1D5 U1.1D7 U1.1E4 U1.1E6 U1.1E8 U1.1F5 U1.1F7 U1.1G6 U1.1G8 U4.5 | length 48.1
  Top Layer w0.15: U4.5@14.925,87 v1(14.925,87.8)
  Top Layer w0.175: C34.2@15.925,92.125 C34.2@16,92.2 ; v1@16.5,91.65 v1(16.55,91.7) ; v1@28.9,69 U1.1D3@29.175,68.725 U1.1E4@29.825,68.075 30.162,67.738 U1.1F5@30.475,67.425 U1.1G6@31.125,66.775 31.175,66.725 v1@31.462,66.437 ; U1.1B3@29.225,69.975 U1.1C4@29.825,69.375 30.162,69.038 U1.1D5@30.475,68.725 U1.1E6@31.125,68.075 31.462,67.738 U1.1F7@31.775,67.425 U1.1F7@31.825,67.375 ; v1@30.188,70.313 U1.1B5@30.475,70.025 U1.1C6@31.125,69.375 31.462,69.038 U1.1D7@31.775,68.725 31.825,68.675 U1.1E8@32.425,68.075 32.475,68.025 U1.1F7@31.825,67.375 ; U1.1G8@32.425,66.775 U1.1F7@31.825,67.375
  Top Layer w0.3: 15.925,91.65 v1@16.5,91.65 ; C34.2@16,92.2 v1(16.55,92.2)
  Top Layer w0.6: L1.2@15.325,91 L1.2@15.475,91 15.725,91 15.925,91.2 15.925,91.65 C34.2@15.925,92.1
  Signal Layer 2 w0.175: v1(14.925,87.8) 15.4,88.275 21.65,88.275 26,83.925 26,72.125 26.45,71.675
  Bottom Layer w0.175: C36.2@28.3,69.025 28.325,69 28.85,69 28.9,69 29.15,69.25 C35.2@29.55,69.25 29.925,69.25 30.15,69.025 v1@30.225,68.95 ; v1(30.175,67.75) 30.725,67.75 C13.2@30.875,67.6 31.025,67.75 v1(31.475,67.75) ; v1@30.2,68.975 30.625,68.975 30.887,69.237 C14.2@30.9,69.25 ; C37.2@30.875,65.95 31.025,65.95 31.475,66.4 v1(31.475,66.45) ; C14.2@30.875,69.25 C14.2@30.9,69.25 ; v1@31.475,66.475 C30.2@32.1,66.475 ; v1@31.525,69.025 31.487,69.063 31.3,69.25 C14.2@30.9,69.25
  other v1: 28.85,69.05 30.175,69.05 31.475,69.05 30.15,70.35
VDD_USB: C7.2 C52.2 U1.1H7 U4.39 | length 41.7
  Top Layer w0.1: U1.1H7@31.775,66.125 32.15,65.75 32.15,65.325 v1(32.475,65)
  Top Layer w0.2: U4.39@17.275,84.35 18.075,84.35 18.125,84.3 v1(18.625,84.3)
  Top Layer w0.45: v1(18.625,84.3) C52.2@19.175,84.3
  Signal Layer 2 w0.3: v1(18.625,84.3) 19.575,83.35 19.575,82.15 15.6,78.175 15.6,72.55 20.525,67.625 20.525,65.925 24.725,61.725 29.525,61.725 32.475,64.675 v1(32.475,65)
  Bottom Layer w0.175: C7.2@32.475,64.375 v1(32.475,65)
VDDA: C49.2 R42.1 U4.20 | length 24.9
  Top Layer w0.2: 10.475,83.55 U4.20@11.375,83.55
  Top Layer w0.3: v1(9.525,82.6) 10.475,83.55
  Top Layer w0.45: C49.2@8.975,82.6 v1(9.525,82.6)
  Signal Layer 2 w0.3: v1(9.525,82.6) 7.55,80.625 7.55,79.889 8.85,78.589 8.85,77.8 18.85,67.8 v1(19.1,67.8)
  Bottom Layer w0.3: v1(19.1,67.8) R42.1@20.65,67.8
VDDA_1V8: C4.2 C5.2 U1.1B6 U1.1H5 | length 7.9
  Top Layer w0.09: v1(31.45,69.7) v1@31.525,69.625
  Top Layer w0.175: U1.1B6@31.125,70.025 v1(31.45,69.7)
  Top Layer w0.2: v1@30.21,65.765 30.52,66.075 U1.1H5@30.52,66.08
  Signal Layer 2 w0.09: v1(31.45,69.7) 31.45,69.563 31.9,69.113 31.9,69.1
  Signal Layer 2 w0.1: v1@30.2,65.775 v1@30.225,65.775
  Signal Layer 2 w0.175: v1@30.225,65.775 30.425,65.975 31.625,65.975 31.9,66.25 31.9,69.1
  Bottom Layer w0.175: C4.2@29.55,65.95 29.975,65.95 v1@30.15,65.775 ; C5.2@30.9,70 31.2,69.7 v1(31.45,69.7)
  other v1: 30.175,65.8
VREF+: C50.2 C61.2 R41.2 U1.M3 | length 4.4
  Top Layer w0.09: U1.M3@26.975,67.05 U1.M3@26.975,67.075 27.2,67.075 v1@27.375,66.9
  Top Layer w0.1: U1.M3@26.975,67.025 U1.M3@26.975,67.05
  Bottom Layer w0.1: R41.2@23.925,66.725 R41.2@24,66.65
  Bottom Layer w0.12: C50.2@25.25,66.425 C50.2@25.25,66.65
  Bottom Layer w0.175: R41.2@24,66.65 25.25,66.65 C61.2@26.125,66.65
  Bottom Layer w0.2: C61.2@26.125,66.65 26.7,66.65 26.95,66.9 v1(27.4,66.9)
VREF_DDR: C8.2 C26.1 C27.2 C28.1 U1.W16 U2.G3 U2.J9 U4.16 | length 133.4
  Top Layer w0.12: U1.W16@33.475,63.575 33.475,61.2 34.25,60.425 34.25,60.075 C8.2@34.425,59.9
  Top Layer w0.15: C26.1@44.275,68.25 v1(46.275,68.25) ; v1@46.375,68.25 v1(46.275,68.25) ; U2.J9@48.4,68 46.525,68 v1(46.275,68.25) ; U2.G3@52.3,66.7 v1(52.625,67.025) 54.985,67.025
  Top Layer w0.175: 6.625,85.975 6.825,85.975
  Top Layer w0.2: 6.825,85.975 8.475,85.975 C27.2@8.975,85.475 9.15,85.3 10.727,85.3 10.877,85.15 U4.16@11.375,85.15
  Top Layer w0.3: 55,67.01 56.285,67.01 56.575,67.3 C28.1@57.05,67.3
  Top Layer w0.5: 6.625,85.975 5.975,86.625 5.975,91.475 9.775,95.275 35.85,95.275 46.025,85.1 47.7,85.1 58.7,74.1 58.7,68.1 ; C8.2@34.425,59.9 35.05,59.9 35.8,59.15 54.175,59.15 58.7,63.675 58.7,68.1 ; C28.1@57.05,67.3 57.05,67.9 57.25,68.1 58.7,68.1
  Signal Layer 1 w0.3: v1(46.275,68.25) 46.525,68 49.475,68 49.725,67.75 51.3,67.75 52.025,67.025 v1(52.625,67.025)
pads on no net: U1.1A1 U1.1A2 U1.1A5 U1.1B1 U1.1B2 U1.1B4 U1.1C1 U1.1C2 U1.1C8 U1.1D8 U1.1E1 U1.1E9 U1.1F8 U1.1H1 U1.1J1 U1.1J2 U1.1J4 U1.1J7 U1.1J8 U1.A2 U1.A3 U1.A4 U1.A7 U1.A9 U1.A10 U1.A12 U1.A13 U1.A15 U1.A16 U1.B1 U1.B2 U1.B3 U1.B4 U1.B9 U1.B10 U1.B11 U1.B12 U1.B13 U1.B14 U1.B15 U1.C1 U1.C2 U1.C3 U1.C4 U1.C5 U1.C6 U1.C11 U1.C12 U1.C15 U1.C16 U1.D1 U1.D2 U1.D3 U1.E1 U1.E3 U1.E17 U1.F2 U1.G2 U1.G3 U1.G19 U1.H1 U1.H2 U1.H3 U1.H17 U1.H18 U1.J2 U1.J3 U1.J18 U1.J19 U1.K1 U1.K2 U1.K3 U1.L1 U1.L2 U1.L3 U1.L18 U1.M17 U1.M18 U1.N2 U1.N18 U1.N19 U1.P1 U1.P2 U1.P3 U1.P18 U1.R2 U1.R3 U1.T1 U1.T2 U1.T3 U1.U1 U1.U2 U1.U3 U1.U4 U1.U5 U1.U6 U1.U7 U1.U8 U1.U10 U1.U12 U1.U15 U1.U16 U1.V1 U1.V2 U1.V3 U1.V4 U1.V5 U1.V6 U1.V7 U1.V8 U1.V9 U1.V10 U1.V11 U1.V12 U1.V13 U1.V14 U1.V15 U1.V16 U1.W2 U1.W3 U1.W4 U1.W7 U1.W8 U1.W10 U1.W11 U1.W14 U2.A1 U2.A2 U2.A9 U2.A10 U2.B1 U2.B2 U2.B3 U2.B7 U2.B8 U2.B9 U2.B10 U2.C3 U2.C8 U2.D6 U2.D7 U2.D8 U2.D9 U2.E5 U2.E6 U2.E7 U2.J2 U2.K2 U2.K3 U2.L2 U2.L3 U2.N5 U2.N6 U2.N7 U2.P6 U2.P7 U2.P8 U2.P9 U2.R3 U2.R8 U2.T1 U2.T2 U2.T3 U2.T7 U2.T8 U2.T9 U2.T10 U2.U1 U2.U2 U2.U9 U2.U10 U4.2 U4.18 U4.21 U4.23 U4.34 U4.35 U4.38 U5.A1 U5.A2 U5.A7 U5.A8 U5.A9 U5.A10 U5.A11 U5.A12 U5.A13 U5.A14 U5.B1 U5.B7 U5.B8 U5.B9 U5.B10 U5.B11 U5.B12 U5.B13 U5.B14 U5.C1 U5.C3 U5.C5 U5.C7 U5.C8 U5.C9 U5.C10 U5.C11 U5.C12 U5.C13 U5.C14 U5.D1 U5.D2 U5.D3 U5.D4 U5.D12 U5.D13 U5.D14 U5.E1 U5.E2 U5.E3 U5.E5 U5.E8 U5.E9 U5.E10 U5.E12 U5.E13 U5.E14 U5.F1 U5.F2 U5.F3 U5.F10 U5.F12 U5.F13 U5.F14 U5.G1 U5.G2 U5.G3 U5.G10 U5.G12 U5.G13 U5.G14 U5.H1 U5.H2 U5.H3 U5.H5 U5.H12 U5.H13 U5.H14 U5.J1 U5.J2 U5.J3 U5.J12 U5.J13 U5.J14 U5.K1 U5.K2 U5.K3 U5.K6 U5.K7 U5.K10 U5.K12 U5.K13 U5.K14 U5.L1 U5.L2 U5.L3 U5.L12 U5.L13 U5.L14 U5.M1 U5.M2 U5.M3 U5.M7 U5.M8 U5.M9 U5.M10 U5.M11 U5.M12 U5.M13 U5.M14 U5.N1 U5.N3 U5.N6 U5.N7 U5.N8 U5.N9 U5.N10 U5.N11 U5.N12 U5.N13 U5.N14 U5.P1 U5.P2 U5.P7 U5.P8 U5.P9 U5.P10 U5.P11 U5.P12 U5.P13 U5.P14
copper on no net: | length 127.1
  Top Layer w0.09: 25.475,68.075 25.975,68.075 ; 25.48,64.33 26.076,64.33 26.321,64.575 26.475,64.575 ; 25.5,67.825 26.725,67.825 26.975,68.075 ; 25.5,72.075 25.975,72.075 ; 25.525,66.075 25.975,66.075 ; 25.525,70.575 25.975,70.575 ; 25.525,71.575 25.975,71.575 ; 25.55,69.075 25.975,69.075 ; 25.55,71.075 25.975,71.075 ; 25.57,65.83 26.076,65.83 26.161,65.914 26.321,66.075 26.475,66.075 ; 25.575,64.075 25.975,64.075 ; 25.58,63.83 26.076,63.83 26.22,63.974 26.22,64.166 26.379,64.325 26.725,64.325 26.975,64.575 ; 25.58,64.83 26.08,64.83 26.175,64.925 26.325,65.075 26.475,65.075 ; 25.6,64.575 25.975,64.575 ; 25.6,65.075 25.975,65.075 ; 25.6,67.575 25.975,67.575 ; 25.625,71.325 26.225,71.325 26.475,71.075 ; 25.63,71.82 26.08,71.82 26.325,71.575 26.475,71.575 ; 25.745,68.32 26.23,68.32 26.475,68.075 ; 25.78,72.32 26.08,72.32 26.225,72.175 26.225,71.975 26.375,71.825 26.725,71.825 26.975,71.575 ; 25.805,66.82 26.23,66.82 26.475,66.575 ; 25.825,69.325 26.725,69.325 26.975,69.075 ; 25.9,65.32 26.73,65.32 26.975,65.075 ; 25.925,65.49 26.325,65.49 26.41,65.575 26.475,65.575 ; 25.925,68.83 26.076,68.83 26.321,69.075 26.475,69.075 ; 25.95,67.33 26.076,67.33 26.22,67.474 26.22,67.495 26.3,67.575 26.475,67.575 ; 25.975,65.66 26.21,65.66 26.375,65.825 26.725,65.825 26.975,65.575 ; 25.975,69.82 26.105,69.82 26.35,69.575 26.475,69.575 ; 25.98,70.33 26.316,70.33 26.73,70.33 26.975,70.575 ; 26,68.49 26.25,68.49 26.335,68.575 26.475,68.575 ; 26.025,69.99 26.175,69.99 26.34,69.825 26.725,69.825 26.975,69.575 ; 26.025,72.9 26.225,72.7 26.225,72.45 26.475,72.2 26.475,72.075 ; 26.075,70.16 26.246,70.16 26.331,70.075 26.475,70.075 ; 26.175,67.16 26.214,67.16 26.374,67.32 26.72,67.32 26.975,67.575 ; 26.175,73.05 26.475,72.75 26.475,72.575 ; 26.225,63.075 26.225,63.7 26.475,63.95 26.475,64.075 ; 26.299,68.745 26.374,68.82 26.576,68.82 26.72,68.676 26.72,68.625 26.77,68.575 26.975,68.575 ; 26.475,63.2 26.475,63.575 ; 26.55,73 26.725,72.825 26.725,72.325 26.975,72.075 ; 26.73,63.23 26.73,63.83 26.975,64.075 ; 26.85,73.025 26.975,72.9 26.975,72.575 ; 26.975,63.2 26.975,63.575 ; 26.975,66.075 27.3,66.4 v1@27.425,66.4 ; 26.98,71.075 27.055,71.15 v1(27.4,71.15) ; 27.075,73.1 27.225,72.95 27.225,72.325 27.475,72.075 ; 27.225,63.2 27.225,63.825 27.475,64.075 ; 27.3,73.175 27.475,73 27.475,72.575 ; v1(27.35,69.4) 27.425,69.325 27.925,69.325 ; v1@27.375,64.975 27.4,64.975 27.475,64.9 27.475,64.575 27.475,64.63 ; v1@27.4,67.875 27.425,67.9 27.8,67.9 27.925,68.025 ; v1@27.45,69 27.475,69.025 28.275,69.025 28.575,69.325 ; 27.475,62.925 27.475,63.575 ; 27.475,71.575 27.72,71.82 27.72,72.775 27.65,72.845 27.65,73.1 27.525,73.225 ; v1@27.5,65.525 27.55,65.475 27.875,65.475 27.925,65.425 ; 27.73,63.055 27.73,63.83 27.975,64.075 ; 27.87,69.325 27.9,69.35 ; v1(27.9,71.15) 27.9,70.65 27.925,70.625 ; v1(27.9,74.375) 27.96,74.315 27.96,73.412 28,73.372 28,73.025 28,72.988 28.06,72.928 28.06,72.615 28.06,72.34 ; 27.925,66.075 27.925,66.05 v1@28.238,65.737 ; 27.925,69.975 v1@28.263,69.638 ; 27.975,64.575 v1@27.975,65 ; 27.975,71.575 28.22,71.82 28.22,72.176 28.22,72.18 28.06,72.34 ; 28.06,72.35 28.06,72.34 ; 28.225,63.45 28.225,64.325 28.475,64.575 ; 28.395,63.525 28.395,63.9 28.475,63.98 28.475,64.075 ; v1(28.4,71.15) 28.4,71.495 28.475,71.57 ; v1(28.45,65) 28.45,65.275 28.575,65.4 28.575,65.425 ; 28.575,69.975 28.85,69.7 v1@28.85,69.625 ; 28.632,63.818 28.725,63.912 28.725,64.325 28.975,64.575 ; 28.73,63.525 28.73,63.676 28.802,63.748 28.975,63.921 28.975,64.075 ; v1@28.875,65.75 29.725,65.75 29.855,65.62 29.855,65.445 29.875,65.425 ; v1(28.875,74) 29.05,73.825 29.05,72.825 28.975,72.75 28.975,72.575 ; 28.975,63.15 28.975,63.575 ; 29.225,63.425 29.225,63.825 29.475,64.075 ; 29.475,63.2 29.475,63.575 ; 29.475,64.575 29.72,64.33 29.72,63.58 ; v1@29.55,70.3 29.875,69.975 ; 29.73,74.3 29.73,72.32 29.975,72.075 ; 29.89,63.675 29.89,63.99 29.975,64.075 ; 29.975,72.575 29.975,74.325 ; 30.06,63.625 30.06,63.747 30.23,63.917 30.23,64.33 30.475,64.575 ; 30.225,74.225 30.225,72.325 30.475,72.075 ; 30.3,63.1 30.3,63.404 30.23,63.474 30.23,63.676 30.475,63.921 30.475,64.075 ; v1(30.3,71.15) 30.3,70.85 30.475,70.675 ; 30.475,63.075 30.475,63.575 ; 30.475,72.575 30.475,74.175 ; 30.725,63.125 30.725,63.825 30.975,64.075 ; 30.89,72.925 30.89,72.16 30.975,72.075 ; 30.975,63.15 30.975,63.575 ; 30.975,71.575 31.22,71.33 31.576,71.33 31.72,71.474 31.72,71.72 31.75,71.75 31.825,71.825 31.97,71.825 32.071,71.825 32.225,71.979 32.225,73.775 ; 31.075,72.388 31.075,72.325 31.225,72.175 31.225,71.825 31.475,71.575 ; 31.22,63.474 31.22,64.32 31.475,64.575 ; 31.23,72.65 31.23,72.474 31.475,72.229 31.475,72.075 ; 31.39,63.6 31.39,63.99 31.475,64.075 ; 31.475,72.575 31.475,73.775 ; 31.764,63.711 31.975,63.921 31.975,64.075 ; 32.23,63.055 32.23,63.83 32.475,64.075 ; 32.475,63.05 32.475,63.575 ; 32.475,72.075 32.475,73.65 ; 32.725,73.4 32.725,71.825 32.975,71.575 ; 32.89,63.55 32.89,63.821 32.975,63.906 32.975,64.075 ; 33,64.575 32.975,64.575 33.2,64.35 33.22,64.33 33.22,63.91 33.06,63.75 33.06,63.55 ; 33.23,63.28 33.23,63.68 33.475,63.925 33.475,64.075 ; 33.475,64.575 33.72,64.33 33.72,63.97 33.72,61.975
  Top Layer w0.1: 31.725,73.725 31.725,72.325 31.975,72.075 ; 31.975,72.575 31.975,73.7 ; 32.975,72.075 32.975,72.225 33.075,72.325 33.225,72.475 33.225,73.475 ; 32.975,72.575 32.975,73.1 ; 33.475,72.575 33.475,73.38
  Top Layer w0.12: 33.72,61.305 33.72,61.975
  Bottom Layer w0.09: 24.55,68.5 26.725,68.5 27.4,67.825 v1@27.4,67.8 ; 26.225,69.75 26.825,69.75 27.175,69.4 v1@27.4,69.4 ; 26.3,69.4 26.725,69.4 27.175,68.95 27.35,68.95 v1@27.425,68.875 ; 26.65,71.9 v1(27.4,71.15) ; 26.75,66.4 v1(27.4,66.4) ; 26.875,65.5 v1(27.475,65.5) ; 27.175,70.25 27.538,70.25 28.138,69.65 v1(28.2,69.65) ; 27.257,66.055 27.92,66.055 v1@28.225,65.75 ; 27.275,65.85 27.613,65.85 27.781,65.681 28.088,65.375 28.5,65.375 v1@28.875,65.75 ; v1@27.3,68 v1@27.5,68 ; 27.325,70.5 27.55,70.5 28.05,70 28.3,70 28.55,70 v1@28.9,69.65 ; 27.4,63.55 v1(27.4,65) ; 27.55,70.75 27.8,70.75 v1(28.2,70.35) ; 27.575,71.975 27.9,71.65 v1(27.9,71.15) ; 27.95,63.425 v1(27.95,65) ; 28.25,63.45 28.25,64.8 v1(28.45,65) ; v1(28.4,71.15) 28.4,72.1 ; 29.025,71.7 29.025,71.475 28.95,71.4 28.95,70.9 v1@29.575,70.275 ; 30.095,72.4 30.095,71.38 v1@30.3,71.175
  Bottom Layer w0.1: 26.025,65.675 26.75,66.4 ; 31.8,63.35 31.975,63.525 v1(31.975,65)
  other v1: 32.975,65 28.2,65.75 28.85,65.8 27.4,67.9 27.4,68.9 28.85,69.65 29.5,70.35

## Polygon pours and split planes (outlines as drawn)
GND on Signal Layer 2 "GND_L2" (solid, pour order 140): 0.4,119.6 85.575,119.6 85.575,0.425 0.4,0.425
VDD2_DDR on Signal Layer 2 "VDD2_DDR" (solid, remove dead copper, pour order 81): 32.15,82.075 32.177,71.402 32.199,71.376 32.243,71.376 32.243,59 55.75,59 55.75,75.85 36.45,75.85 36.45,89.675 30.55,95.575 12.275,95.575 12.275,91.975 13.3,91.975 14.125,92.8 27.2,92.8 32.192,87.808
VDD on Signal Layer 2 "VDD" (solid, remove dead copper, pour order 86): 14.985,77.625 24.393,63.925 30.539,63.925 30.539,66.825 30.414,66.95 29.489,67.875 23.928,69.432 17.27,77.625
VDD_CORE on Signal Layer 2 "VDD_CORE" (solid, remove dead copper, pour order 88): 26.225,84.05 20.8,89.475 16.125,89.475 16.125,92.45 26.325,92.45 29.375,89.4 31.75,87.024 31.75,65.575 30.396,65.575 30.396,67.08 29.319,68.059 29.153,68.209 26.225,68.209
5V_VIN on Signal Layer 2 "5V_VIN" (solid, remove dead copper, pour order 94): 12.675,88.875 12.675,88.1 9.35,88.1 9.325,88.075 9.319,87 9.328,80.375 18.55,80.375 19.325,81.15 19.325,83.25 17.25,83.25 17.25,88.875
GND on Top Layer "GND_L01_P138" (solid, remove dead copper, pour order 138): 0.35,119.45 0.35,0.775 85.65,0.775 85.65,119.45
5V_VIN on Top Layer "5V_VIN" (solid, remove dead copper, pour order 122): 10.825,88.7 10.725,88.8 9.925,88.8 9.825,88.7 9.825,87.925 11.15,86.6 12.125,86.6 12.225,86.7 12.225,87.5 11.925,87.8 11.325,87.8 10.825,88.3
NetL2_1 on Top Layer "NetL2_1" (solid, remove dead copper, pour order 119): 12.625,88.5 12.625,87.8 12.6,87.775 12.425,87.775 12.1,88.1 11.425,88.1 11.025,88.5 11.025,89.9 11.225,90.1 12.825,90.1 13.025,89.9 13.025,88.9
5V_VIN on Top Layer "5V_VIN" (solid, remove dead copper, pour order 106): 13.225,89.6 13.125,89.5 13.125,88.6 13.425,88.3 13.725,88.3 14.225,88.8 14.225,89.6
NetL1_1 on Top Layer "NetL1_1" (solid, remove dead copper, pour order 115): 16.375,89.9 14.425,89.9 14.425,88.8 14.025,88.4 14.025,88.1 14.125,88 14.525,88 15.325,88.8 16.225,88.8 16.375,88.95
5V_VIN on Top Layer "5V_VIN" (solid, remove dead copper, pour order 104): 10.825,79.4 9.925,79.4 9.825,79.5 9.825,80.3 11.125,81.6 12.325,81.6 12.425,81.7 12.425,82.5 12.625,82.5 12.625,81.2 12.525,81.1 12.125,80.7 11.325,80.7 10.975,80.35 10.975,79.6
NetL4_1 on Top Layer "NetL4_1" (solid, remove dead copper, pour order 114): 12.825,81.2 12.825,82.5 13.025,82.5 13.025,79.6 12.725,79.3 11.225,79.3 11.125,79.4 11.125,80.3 11.425,80.6 12.225,80.6
NetL3_1 on Top Layer "NetL3_1" (solid, remove dead copper, pour order 116): 14.425,82.5 14.625,82.5 14.625,81.3 14.725,81.2 14.925,81.2 15.525,80.6 16.025,80.6 16.4,80.225 16.4,79.575 16.125,79.3 14.425,79.3 14.425,80.4
5V_VIN on Top Layer "NetC47_2" (solid, remove dead copper, pour order 117): 14.025,82.5 14.025,81.6 13.725,81.3 13.725,80.7 13.425,80.4 13.225,80.4 13.125,80.3 13.125,79.8 13.225,79.7 14.125,79.7 14.225,79.8 14.225,80.4 14.325,80.5 14.325,82.4 14.225,82.5
GND on Signal Layer 1 "GND" (solid, remove dead copper, pour order 96): 0.408,119.592 85.592,119.592 85.592,0.408 0.408,0.408
GND on Bottom Layer "gnd" (solid, pour order 142): -0.125,120 85.875,120 85.875,0.3 85.725,0.15 -0.125,0.15

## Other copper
Top Layer:
  pour cut-out: 32.825,76.775 57.375,76.775 57.375,59.275 32.825,59.275
  pour cut-out: 32.825,76.775 57.375,76.775 57.375,59.275 57.35,59.25 57.325,59.275 32.825,59.275
  pour cut-out: 11.825,82.5 11.825,86.6 16.825,86.6 16.825,82.5
Bottom Layer:
  pour cut-out: 30.788,61.1 55.625,61.1 55.625,75.625 30.788,75.625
